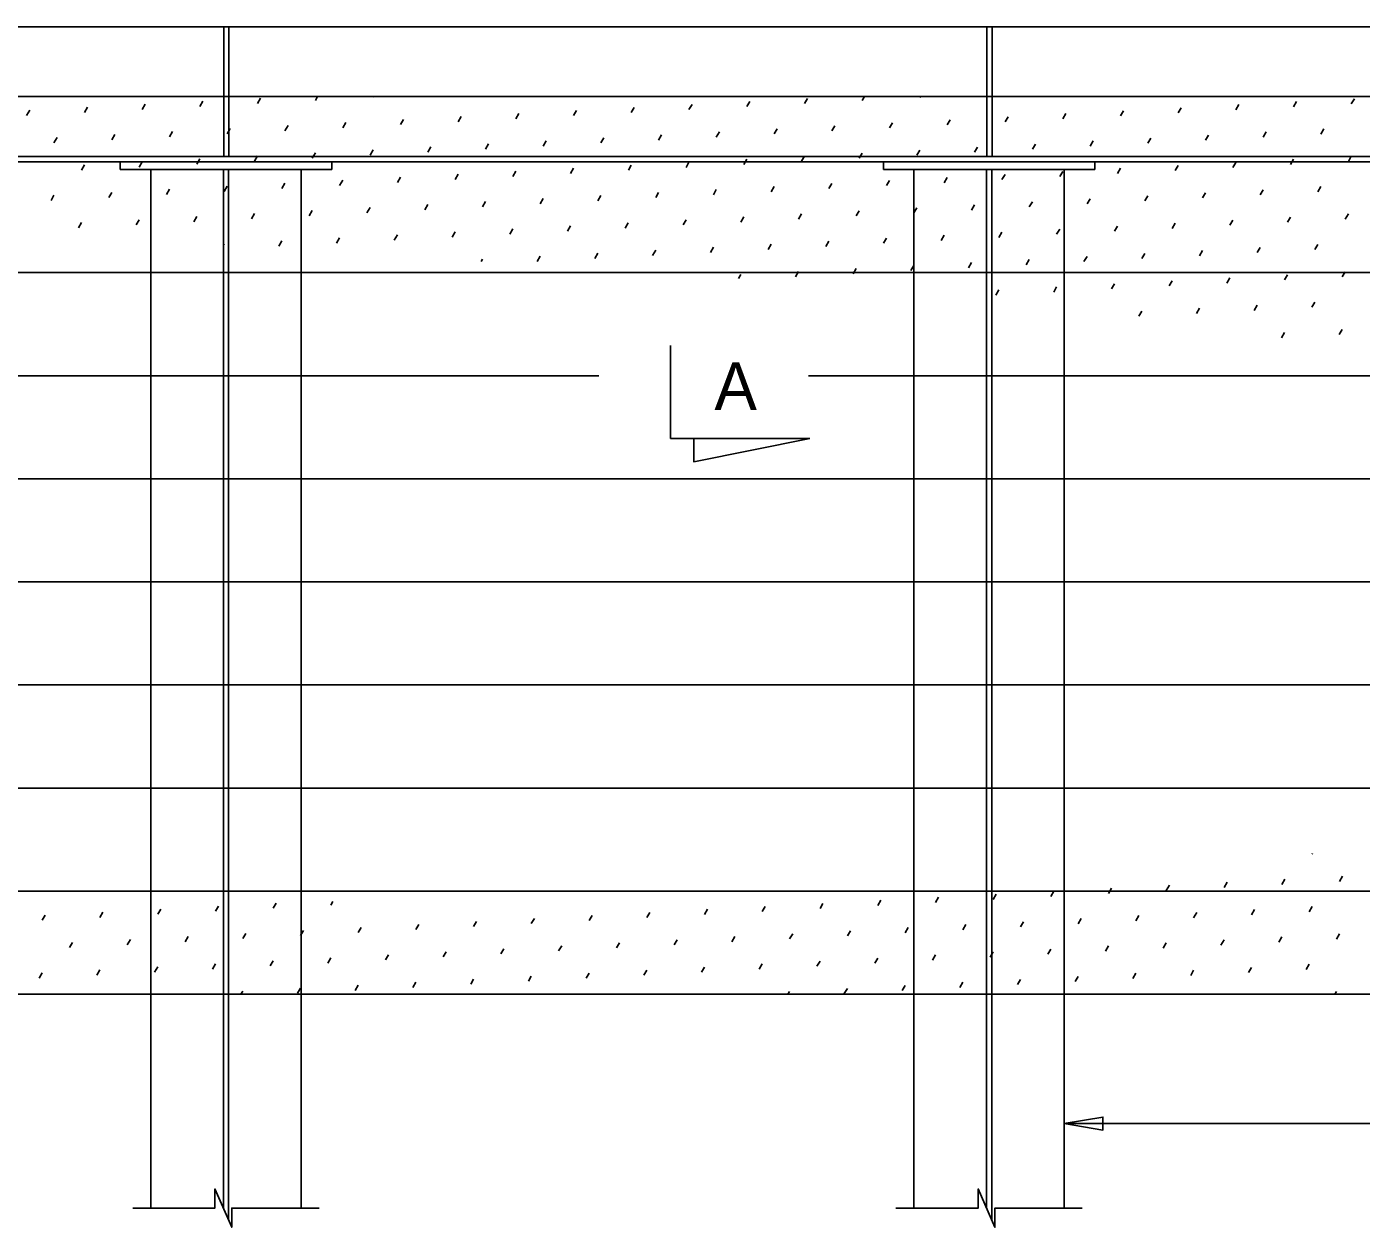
# Model space of a CAD drawing. Extents: x 0 to 61.6, y 0 to 38.9.
# Drawn here: x 30.2 to 40.98, y 14.06 to 23.77 of the extents above; entities that cross this region are included whole.
import ezdxf

# ---------------------------------------------------------------- set-up
doc = ezdxf.new("R2010")
doc.units = 0
for name, color, linetype in [('Dimension', 7, 'Continuous'), ('GroundLines', 7, 'Continuous'), ('SteelMisc', 7, 'Continuous'), ('SteelMisc_h', 7, 'Continuous'), ('Symbols', 7, 'Continuous'), ('TextStructures', 7, 'Continuous'), ('Wood', 7, 'Continuous'), ('Wood_h', 7, 'Continuous')]:
    doc.layers.add(name, color=color, linetype=linetype)

msp = doc.modelspace()

# ---------------------------------------------------------------- linework, layer by layer
at = {"layer": 'Dimension'}
for p, q in [((32.064, 23.148), (32.089, 23.19)), ((32.531, 23.172), (32.549, 23.203)), ((32.997, 23.197), (33.001, 23.203)), ((36.483, 23.146), (36.508, 23.188)), ((36.95, 23.171), (36.969, 23.203)), ((37.416, 23.195), (37.421, 23.203)), ((30.198, 23.051), (30.223, 23.093)), ((30.665, 23.075), (30.689, 23.117)), ((31.131, 23.099), (31.156, 23.141)), ((31.598, 23.124), (31.622, 23.166)), ((34.617, 23.049), (34.642, 23.091)), ((35.084, 23.073), (35.108, 23.115)), ((35.55, 23.098), (35.575, 23.14)), ((36.017, 23.122), (36.041, 23.164)), ((39.036, 23.047), (39.061, 23.089)), ((39.503, 23.071), (39.527, 23.113)), ((39.969, 23.096), (39.994, 23.138)), ((40.436, 23.12), (40.46, 23.162)), ((40.902, 23.144), (40.927, 23.186)), ((32.752, 22.951), (32.776, 22.993)), ((33.218, 22.976), (33.242, 23.018)), ((33.685, 23), (33.709, 23.042)), ((34.151, 23.024), (34.175, 23.066)), ((37.171, 22.95), (37.195, 22.992)), ((37.637, 22.974), (37.661, 23.016)), ((38.104, 22.998), (38.128, 23.04)), ((38.57, 23.023), (38.594, 23.065)), ((30.419, 22.83), (30.444, 22.872)), ((30.886, 22.854), (30.91, 22.896)), ((31.352, 22.878), (31.377, 22.92)), ((31.819, 22.903), (31.843, 22.945)), ((32.285, 22.927), (32.31, 22.969)), ((34.838, 22.828), (34.863, 22.87)), ((35.305, 22.852), (35.329, 22.894)), ((35.771, 22.876), (35.796, 22.918)), ((36.238, 22.901), (36.262, 22.943)), ((36.704, 22.925), (36.729, 22.967)), ((39.257, 22.826), (39.282, 22.868)), ((39.724, 22.85), (39.748, 22.892)), ((40.19, 22.875), (40.215, 22.917)), ((40.657, 22.899), (40.681, 22.941)), ((32.973, 22.73), (32.997, 22.772)), ((33.439, 22.755), (33.463, 22.797)), ((33.906, 22.779), (33.93, 22.821)), ((34.372, 22.803), (34.396, 22.845)), ((37.392, 22.729), (37.416, 22.771)), ((37.858, 22.753), (37.882, 22.795)), ((38.325, 22.777), (38.349, 22.819)), ((38.791, 22.802), (38.815, 22.844)), ((30.641, 22.609), (30.665, 22.651)), ((31.107, 22.633), (31.131, 22.675)), ((31.573, 22.657), (31.598, 22.699)), ((32.04, 22.682), (32.064, 22.724)), ((32.506, 22.706), (32.531, 22.748)), ((35.06, 22.607), (35.084, 22.649)), ((35.526, 22.631), (35.55, 22.673)), ((35.992, 22.655), (36.017, 22.697)), ((36.459, 22.68), (36.483, 22.722)), ((36.925, 22.704), (36.95, 22.746)), ((39.945, 22.629), (39.969, 22.671)), ((40.411, 22.654), (40.436, 22.696)), ((40.878, 22.678), (40.902, 22.72)), ((33.194, 22.509), (33.218, 22.551)), ((33.66, 22.534), (33.685, 22.576)), ((34.127, 22.558), (34.151, 22.6)), ((34.593, 22.582), (34.617, 22.624)), ((37.613, 22.507), (37.637, 22.549)), ((38.079, 22.532), (38.104, 22.574)), ((38.546, 22.556), (38.57, 22.598)), ((39.012, 22.581), (39.036, 22.623)), ((39.479, 22.605), (39.503, 22.647)), ((31.328, 22.412), (31.352, 22.454)), ((31.794, 22.436), (31.819, 22.478)), ((32.261, 22.461), (32.285, 22.503)), ((32.727, 22.485), (32.752, 22.527)), ((35.747, 22.41), (35.771, 22.452)), ((36.213, 22.434), (36.238, 22.476)), ((36.68, 22.459), (36.704, 22.501)), ((37.146, 22.483), (37.171, 22.525)), ((40.166, 22.408), (40.19, 22.45)), ((40.632, 22.433), (40.657, 22.475)), ((30.395, 22.363), (30.419, 22.405)), ((30.862, 22.387), (30.886, 22.429)), ((33.415, 22.288), (33.439, 22.33)), ((33.881, 22.313), (33.906, 22.355)), ((34.348, 22.337), (34.372, 22.379)), ((34.814, 22.361), (34.838, 22.403)), ((35.281, 22.386), (35.305, 22.428)), ((37.834, 22.286), (37.858, 22.328)), ((38.3, 22.311), (38.325, 22.353)), ((38.767, 22.335), (38.791, 22.377)), ((39.233, 22.36), (39.257, 22.401)), ((39.7, 22.384), (39.724, 22.426)), ((31.549, 22.191), (31.573, 22.233)), ((32.015, 22.215), (32.04, 22.257)), ((32.482, 22.24), (32.506, 22.282)), ((32.948, 22.264), (32.973, 22.306)), ((35.968, 22.189), (35.992, 22.231)), ((36.434, 22.213), (36.459, 22.255)), ((36.901, 22.238), (36.925, 22.28)), ((37.367, 22.262), (37.392, 22.304)), ((40.387, 22.187), (40.411, 22.229)), ((40.853, 22.212), (40.878, 22.254)), ((30.616, 22.142), (30.64, 22.184)), ((31.083, 22.166), (31.107, 22.208)), ((33.636, 22.067), (33.66, 22.109)), ((34.102, 22.092), (34.127, 22.134)), ((34.569, 22.116), (34.593, 22.158)), ((35.035, 22.14), (35.059, 22.182)), ((35.502, 22.165), (35.526, 22.207)), ((38.521, 22.09), (38.546, 22.132)), ((38.988, 22.114), (39.012, 22.156)), ((39.454, 22.138), (39.478, 22.18)), ((39.921, 22.163), (39.945, 22.205)), ((31.792, 22.008), (31.794, 22.012)), ((32.237, 21.994), (32.261, 22.036)), ((32.703, 22.018), (32.727, 22.06)), ((33.169, 22.043), (33.194, 22.085)), ((36.189, 21.968), (36.213, 22.01)), ((36.656, 21.992), (36.68, 22.034)), ((37.122, 22.017), (37.146, 22.059)), ((37.588, 22.041), (37.613, 22.083)), ((38.055, 22.065), (38.079, 22.107)), ((40.608, 21.966), (40.632, 22.008)), ((34.323, 21.871), (34.348, 21.913)), ((34.79, 21.895), (34.814, 21.937)), ((35.256, 21.919), (35.281, 21.961)), ((35.723, 21.944), (35.747, 21.986)), ((38.742, 21.869), (38.767, 21.911)), ((39.209, 21.893), (39.233, 21.935)), ((39.675, 21.917), (39.7, 21.959)), ((40.142, 21.942), (40.166, 21.984)), ((33.871, 21.87), (33.881, 21.888)), ((36.41, 21.747), (36.434, 21.789)), ((36.877, 21.771), (36.901, 21.813)), ((37.343, 21.796), (37.367, 21.838)), ((37.809, 21.82), (37.834, 21.862)), ((38.276, 21.844), (38.3, 21.886)), ((40.829, 21.745), (40.853, 21.787)), ((35.949, 21.732), (35.968, 21.765)), ((38.963, 21.648), (38.988, 21.69)), ((39.43, 21.672), (39.454, 21.714)), ((39.896, 21.696), (39.921, 21.738)), ((40.363, 21.721), (40.387, 21.763)), ((38.03, 21.599), (38.055, 21.641)), ((38.497, 21.623), (38.521, 21.665)), ((39.184, 21.427), (39.209, 21.469)), ((39.651, 21.451), (39.675, 21.493)), ((40.117, 21.475), (40.142, 21.517)), ((40.584, 21.5), (40.608, 21.542)), ((40.338, 21.254), (40.363, 21.296)), ((40.805, 21.279), (40.829, 21.321)), ((40.586, 17.081), (40.588, 17.086)), ((39.407, 16.787), (39.432, 16.829)), ((39.874, 16.811), (39.898, 16.853)), ((40.34, 16.835), (40.364, 16.877)), ((40.807, 16.86), (40.831, 16.902)), ((37.541, 16.689), (37.566, 16.731)), ((38.008, 16.714), (38.032, 16.756)), ((38.474, 16.738), (38.499, 16.78)), ((38.941, 16.762), (38.965, 16.804)), ((30.79, 16.569), (30.815, 16.611)), ((31.257, 16.594), (31.281, 16.636)), ((31.723, 16.618), (31.747, 16.66)), ((32.19, 16.642), (32.214, 16.684)), ((32.656, 16.667), (32.673, 16.697)), ((35.209, 16.567), (35.234, 16.609)), ((35.676, 16.592), (35.7, 16.634)), ((36.142, 16.616), (36.166, 16.658)), ((36.609, 16.64), (36.633, 16.682)), ((37.075, 16.665), (37.099, 16.707)), ((40.095, 16.59), (40.119, 16.632)), ((40.561, 16.614), (40.585, 16.656)), ((30.324, 16.545), (30.348, 16.587)), ((33.344, 16.47), (33.368, 16.512)), ((33.81, 16.494), (33.834, 16.536)), ((34.276, 16.519), (34.301, 16.561)), ((34.743, 16.543), (34.767, 16.585)), ((37.763, 16.468), (37.787, 16.51)), ((38.229, 16.492), (38.253, 16.534)), ((38.695, 16.517), (38.72, 16.559)), ((39.162, 16.541), (39.186, 16.583)), ((39.628, 16.566), (39.653, 16.608)), ((31.478, 16.372), (31.502, 16.414)), ((31.944, 16.397), (31.969, 16.439)), ((32.411, 16.421), (32.435, 16.463)), ((32.877, 16.446), (32.901, 16.488)), ((35.897, 16.371), (35.921, 16.413)), ((36.363, 16.395), (36.388, 16.437)), ((36.83, 16.419), (36.854, 16.461)), ((37.296, 16.444), (37.32, 16.486)), ((40.316, 16.369), (40.34, 16.411)), ((40.782, 16.393), (40.807, 16.435)), ((30.545, 16.324), (30.569, 16.366)), ((31.011, 16.348), (31.036, 16.39)), ((33.565, 16.249), (33.589, 16.291)), ((34.031, 16.273), (34.055, 16.315)), ((34.497, 16.298), (34.522, 16.34)), ((34.964, 16.322), (34.988, 16.364)), ((35.43, 16.346), (35.455, 16.388)), ((37.984, 16.247), (38.008, 16.289)), ((38.45, 16.271), (38.474, 16.313)), ((38.916, 16.296), (38.941, 16.338)), ((39.383, 16.32), (39.407, 16.362)), ((39.849, 16.345), (39.874, 16.386)), ((31.699, 16.151), (31.723, 16.193)), ((32.165, 16.176), (32.19, 16.218)), ((32.632, 16.2), (32.656, 16.242)), ((33.098, 16.225), (33.122, 16.267)), ((36.118, 16.15), (36.142, 16.192)), ((36.584, 16.174), (36.609, 16.216)), ((37.051, 16.198), (37.075, 16.24)), ((37.517, 16.223), (37.541, 16.265)), ((40.537, 16.148), (40.561, 16.19)), ((30.299, 16.078), (30.324, 16.12)), ((30.766, 16.103), (30.79, 16.145)), ((31.232, 16.127), (31.257, 16.169)), ((33.786, 16.028), (33.81, 16.07)), ((34.252, 16.052), (34.276, 16.094)), ((34.718, 16.077), (34.743, 16.119)), ((35.185, 16.101), (35.209, 16.143)), ((35.651, 16.125), (35.676, 16.167)), ((38.671, 16.05), (38.695, 16.092)), ((39.137, 16.075), (39.162, 16.117)), ((39.604, 16.099), (39.628, 16.141)), ((40.07, 16.123), (40.095, 16.165)), ((31.929, 15.947), (31.944, 15.972)), ((32.386, 15.955), (32.411, 15.997)), ((32.853, 15.979), (32.877, 16.021)), ((33.319, 16.003), (33.343, 16.045)), ((36.349, 15.947), (36.363, 15.971)), ((36.805, 15.953), (36.83, 15.995)), ((37.272, 15.977), (37.296, 16.019)), ((37.738, 16.002), (37.762, 16.044)), ((38.205, 16.026), (38.229, 16.068)), ((40.769, 15.947), (40.782, 15.969)), ((31.477, 15.947), (31.478, 15.948)), ((45.448, 14.902), (38.583, 14.902))]:
    msp.add_line(p, q, dxfattribs=at)
msp.add_lwpolyline([(38.583, 14.902), (38.895, 14.849), (38.895, 14.955)], close=True, dxfattribs=at)
at = {"layer": 'GroundLines'}
msp.add_line((4.623, 17.613), (45.665, 17.613), dxfattribs=at)
at = {"layer": 'SteelMisc'}
for p, q in [((6.534, 23.768), (44.75, 23.768)), ((31.791, 22.712), (31.791, 23.768)), ((31.832, 22.712), (31.832, 23.768)), ((37.958, 22.712), (37.958, 23.768)), ((37.999, 22.712), (37.999, 23.768)), ((6.288, 22.676), (44.996, 22.676)), ((6.534, 22.718), (44.75, 22.718)), ((30.954, 22.613), (30.954, 22.676)), ((32.663, 22.613), (32.663, 22.676)), ((37.121, 22.613), (37.121, 22.676)), ((38.83, 22.613), (38.83, 22.676)), ((30.954, 22.613), (32.663, 22.613)), ((31.201, 17.613), (31.201, 22.613)), ((32.416, 17.613), (32.416, 22.613)), ((37.121, 22.613), (38.83, 22.613)), ((37.368, 17.613), (37.368, 22.613)), ((38.583, 17.613), (38.583, 22.613))]:
    msp.add_line(p, q, dxfattribs=at)
at = {"layer": 'SteelMisc_h'}
for p, q in [((31.788, 14.219), (31.788, 22.613)), ((31.83, 14.122), (31.83, 22.613)), ((37.954, 14.219), (37.954, 22.613)), ((37.996, 14.122), (37.996, 22.613)), ((31.201, 14.219), (31.201, 17.613)), ((32.416, 14.219), (32.416, 17.613)), ((37.368, 14.219), (37.368, 17.613)), ((38.583, 14.219), (38.583, 17.613))]:
    msp.add_line(p, q, dxfattribs=at)
at = {"layer": 'Symbols'}
for points in [[(35.589, 20.44), (35.401, 20.44), (35.401, 21.19)], [(31.055, 14.219), (31.72, 14.219), (31.72, 14.374), (31.855, 14.064), (31.855, 14.219), (32.561, 14.219)], [(37.222, 14.219), (37.887, 14.219), (37.887, 14.374), (38.022, 14.064), (38.022, 14.219), (38.728, 14.219)]]:
    msp.add_lwpolyline(points, dxfattribs=at)
msp.add_lwpolyline([(36.526, 20.44), (35.589, 20.44), (35.589, 20.252)], close=True, dxfattribs=at)
at = {"layer": 'TextStructures'}
msp.add_line((6.534, 23.203), (44.786, 23.203), dxfattribs=at)
at = {"layer": 'Wood'}
for p, q in [((31.201, 21.78), (26.25, 21.78)), ((37.368, 21.78), (32.416, 21.78)), ((43.534, 21.78), (38.583, 21.78)), ((31.201, 20.947), (26.25, 20.947)), ((34.821, 20.947), (32.416, 20.947)), ((37.368, 20.947), (36.516, 20.947)), ((43.534, 20.947), (38.583, 20.947)), ((31.201, 20.113), (26.25, 20.113)), ((37.368, 20.113), (32.416, 20.113)), ((43.534, 20.113), (38.583, 20.113)), ((31.201, 19.28), (26.25, 19.28)), ((37.368, 19.28), (32.416, 19.28)), ((43.534, 19.28), (38.583, 19.28)), ((31.201, 18.447), (26.25, 18.447)), ((37.368, 18.447), (32.416, 18.447)), ((43.534, 18.447), (38.583, 18.447))]:
    msp.add_line(p, q, dxfattribs=at)
at = {"layer": 'Wood_h'}
for p, q in [((32.416, 21.78), (31.201, 21.78)), ((38.583, 21.78), (37.368, 21.78)), ((32.416, 20.947), (31.201, 20.947)), ((38.583, 20.947), (37.368, 20.947)), ((32.416, 20.113), (31.201, 20.113)), ((38.583, 20.113), (37.368, 20.113)), ((32.416, 19.28), (31.201, 19.28)), ((38.583, 19.28), (37.368, 19.28)), ((32.416, 18.447), (31.201, 18.447)), ((38.583, 18.447), (37.368, 18.447)), ((44.75, 16.78), (6.534, 16.78)), ((44.75, 15.947), (6.534, 15.947))]:
    msp.add_line(p, q, dxfattribs=at)

# ---------------------------------------------------------------- texts
at = {"layer": 'TextStructures'}
msp.add_text('A', height=0.384, dxfattribs=at).set_placement((35.756, 20.671))

doc.saveas('drawing.dxf')
